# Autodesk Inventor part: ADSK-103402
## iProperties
Shininess: 20.0
Created: 2001-04
Part Number: ADSK-103402
Document SubType Name: Modeling
Designer: Administrator
Stock Number: ADSK-103402
Density: 1 g/cm^3
Density: 0.0
Volumn: 0.0
Area: 0.0
PropertySet Name: Model Information
Control State: 0
Master: False
Checked Out: False
Author: Administrator
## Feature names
1. Sweep1
